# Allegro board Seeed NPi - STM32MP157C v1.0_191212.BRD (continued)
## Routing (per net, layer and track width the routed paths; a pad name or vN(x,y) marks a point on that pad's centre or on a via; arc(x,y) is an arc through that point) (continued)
GND_EARTH: length 211.8
  TOP w0.121: 54.31,12.11 54.9,12.11 55.46,11.55 v1(55.46,10.77)
  TOP w0.375: 1.69,35.81 J2.S1 ; J2.S1 2.95,36.56 ; J2.S1 1.69,37.32 ; 1.94,32.61 J2.S5 0.79,33.76 ; J8.S3 19.86,8.29 ; J8.S3 19.86,4.94 ; J8.S3 21.54,6.61 ; J13.16 39.95,10.17 ; J13.16 38.44,11.67 ; J13.16 38.44,8.67 ; J2.S6 1.94,31.92 ; J2.S6 1.94,29.61 ; J2.S6 0.79,30.76 ; 6.72,4.94 J8.S4 8.4,6.61 ; 21.44,10.17 J13.15 ; J13.15 24.45,10.17 ; J13.15 22.94,8.67 ; 1.69,28.72 J2.S3 1.69,27.21
  TOP w0.381: J1.6 1.67,54.46 ; 1.67,54.46 1.57,54.46 0.54,53.44 ; 1.67,54.46 0.54,55.6 ; 0.92,20.42 0.92,20.92 J4.1 1.15,25.85 1.15,26.24 ; 1.9,39.91 J5.6 1.5,39.91 ; 1.5,50.71 J5.5 1.9,50.71 ; 1.5,50.71 1.49,50.71 0.54,51.66 ; 1.5,50.71 0.54,49.76 ; 55.41,13.81 55.41,13.56 54.31,12.47 J20.3 54.31,12.11 55.41,11.02 ; 55.41,17.62 54.31,18.72 J20.4 54.31,20.49 54.26,20.55 ; 1.7,65.26 0.54,64.11 ; 1.7,65.26 1.54,65.26 0.44,66.36 ; 1.7,65.26 J1.5 ; 1.5,39.91 0.54,40.87 ; 1.5,39.91 1.49,39.91 0.54,38.96 ; 54.9,20.93 54.9,21.1 J18.1 54.9,25.9 54.9,26.26 ; 0.8,78.84 0.84,78.84 J3.1 6.13,84.13 6.13,84.17
  TOP w0.508: J2.S5 v1(1.94,35.02)
  LYR2_GND w0.375: J13.15 24.45,10.17 ; J13.15 21.44,10.17 ; J13.15 22.94,8.67 ; 8.4,6.61 J8.S4 6.72,4.94 ; 1.69,28.72 J2.S3 1.69,27.21 ; J13.16 38.44,11.67 ; J13.16 38.44,8.67 ; J13.16 39.95,10.17 ; J8.S3 19.86,8.29 ; J8.S3 21.54,6.61 ; J8.S3 19.86,4.94 ; J2.S1 1.69,37.32 ; J2.S1 2.95,36.56 ; J2.S1 1.69,35.81
  LYR3 w0.375: 1.69,35.81 J2.S1 ; J2.S1 1.69,37.32 ; J2.S1 2.95,36.56 ; J13.16 38.44,11.67 ; J13.16 38.44,8.67 ; J13.16 39.95,10.17 ; 21.44,10.17 J13.15 ; J13.15 24.45,10.17 ; J13.15 22.94,8.67 ; 1.69,28.72 J2.S3 1.69,27.21 ; 19.86,4.94 J8.S3 ; J8.S3 19.86,8.29 ; J8.S3 21.54,6.61 ; 6.72,4.94 J8.S4 8.4,6.61
  LYR4 w0.375: 22.94,8.67 J13.15 ; J13.15 21.44,10.17 ; J13.15 24.45,10.17 ; 1.69,27.21 J2.S3 1.69,28.72 ; J2.S1 2.95,36.56 ; J2.S1 1.69,35.81 ; J2.S1 1.69,37.32 ; 6.72,4.94 J8.S4 8.4,6.61 ; J13.16 39.95,10.17 ; J13.16 38.44,11.67 ; J13.16 38.44,8.67 ; J8.S3 19.86,8.29 ; J8.S3 19.86,4.94 ; J8.S3 21.54,6.61
  LYR5_PWR w0.375: J2.S1 1.69,37.32 ; J2.S1 1.69,35.81 ; J2.S1 2.95,36.56 ; 1.69,27.21 J2.S3 1.69,28.72 ; J13.15 24.45,10.17 ; J13.15 22.94,8.67 ; J13.15 21.44,10.17 ; 6.72,4.94 J8.S4 8.4,6.61 ; 19.86,4.94 J8.S3 ; J8.S3 19.86,8.29 ; J8.S3 21.54,6.61 ; J13.16 39.95,10.17 ; J13.16 38.44,8.67 ; J13.16 38.44,11.67
  LYR5_PWR w0.508: 6,84.17 6,84 J3.1 0.96,78.97 0.92,78.97 ; 0.92,20.93 0.93,20.93 J4.1 3.5,24.19 1.3,26.39 ; 55.15,26.13 55.13,26.13 J18.1 54.95,21.05 55.15,21.05
  BOTTOM w0.375: 21.44,10.17 J13.15 ; J13.15 24.45,10.17 ; J13.15 22.94,8.67 ; J2.S1 1.69,37.32 ; J2.S1 2.95,36.56 ; J2.S1 1.69,35.81 ; 38.44,8.67 J13.16 ; J13.16 39.95,10.17 ; J13.16 38.44,11.67 ; 6.72,4.94 J8.S4 8.4,6.61 ; 19.86,4.94 J8.S3 ; J8.S3 21.54,6.61 ; J8.S3 19.86,8.29 ; 1.69,27.21 J2.S3 1.69,28.72
  BOTTOM w0.381: 1.05,78.58 1.05,79.05 J3.1 6.04,84.05 6.13,84.05
  vias: v1(0.49,77.36) v1(0.49,72.28) v1(0.49,67.2) v1(0.49,62.12) v1(0.49,57.04) v1(0.49,51.96) v1(0.49,13.23) v1(0.52,46.3) v1(0.52,41.22) v1(0.54,38.6) v1(0.59,35.56) v1(0.54,33.63) v1(0.54,30.76) v1(0.59,20.14) v1(0.57,16.63) v1(0.52,11.63) v1(0.57,9.22) v1(0.54,5.56) v1(0.54,3.27) v1(0.72,26.64) v1(2.01,0.86) v1(3.82,0.68) v1(6.79,4.16) v1(6.97,84.35) v1(8.9,0.68) v1(12.05,84.35) v1(16.26,0.68) v1(17.13,84.35) v1(18.93,4.62) v1(21.09,4.72) v1(21.34,0.68) v1(22.21,84.35) v1(23.3,0.66) v1(27.29,84.35) v1(28.38,0.66) v1(32.37,84.35) v1(33.46,0.66) v1(34.32,84.3) v1(36.25,0.66) v1(39.58,3.73) v1(39.63,7.41) v1(40.8,0.71) v1(45.88,0.71) v1(50.96,0.71) v1(55.46,77.42) v1(55.46,72.34) v1(55.46,67.26) v1(55.46,62.18) v1(55.46,57.1) v1(55.46,52.02) v1(55.46,46.94) v1(55.46,41.86) v1(55.46,36.78) v1(55.46,31.7) v1(55.46,16.74) v1(55.46,5.69)
VBAT: length 41.2
  TOP w0.203: J7.25 44.62,44 v1(44.99,44.37) ; J7.27 v1(44.46,44.4)
  TOP w0.508: v1(44.46,44.4) 44.97,44.4 v1(44.99,44.37)
  LYR3 w0.508: v1(49.31,14.32) 49.3,14.32 v1(48.8,14.32) 48.8,15.59 43.65,20.74 43.65,27.08 v1(48.42,31.85)
  BOTTOM w0.508: v1(44.46,44.4) 44.97,44.4 v1(44.99,44.37) 46.44,44.37 48.81,42 48.81,32.23 v1(48.42,31.85)
26M_XTAL_IN: length 8.4
  TOP w0.254: X1.3 27.45,74.09 C8.1 28.64,74.09 29.04,74.48 29.04,74.49 29.4,74.84 R29.2 29.97,74.84 30.25,75.13 33.59,75.13 33.8,74.91 U3.10
26M_XTAL_OUT: length 4.2
  TOP w0.254: U3.11 29.98,74.06 29.97,74.08 R29.1 R30.1
BOOT0: length 39.1
  TOP w0.121: J10.6 31.45,52 30.89,52.55 24.8,52.55 v1(23.27,51.03) ; R8.2 v1(11.39,67.79)
  LYR3 w0.121: v1(23.27,51.03) 23.91,51.66 23.91,57.5 20.35,61.06 20.35,63.6 20.86,64.11 20.86,66.39 v1(21.24,66.77)
  LYR4 w0.121: v1(11.39,67.79) 11.77,68.17 17.31,68.17 18.7,66.77 v1(21.24,66.77)
BOOT1: length 38.7
  TOP w0.121: v1(23.27,50.39) 25.05,52.17 30.77,52.17 31.34,51.6 J10.8 ; v1(16.54,72.49) 16.19,72.49 16.06,72.36 R12.2
  LYR3 w0.121: v1(23.27,50.39) 24.16,51.28 24.16,57.6 20.58,61.19 20.58,63.34 21.12,63.88 21.12,66.01 21.74,66.64 21.74,67.54 21.37,67.92 v1(21.37,69.06)
  LYR4 w0.121: v1(21.37,69.06) 20.33,69.06 16.9,72.49 v1(16.54,72.49)
BOOT2: length 33.3
  TOP w0.121: v1(24.42,50.77) 25.43,51.79 30.56,51.79 31.15,51.2 J10.10 ; v1(13.24,63.6) 12.48,63.6 11.98,64.1 11.98,64.23 11.45,64.76 R3.2
  LYR3 w0.121: v1(20.99,63.09) 20.99,62.74 20.8,62.55 20.8,61.32 24.42,57.7 v1(24.42,50.77)
  LYR4 w0.121: v1(20.99,63.09) 20.61,62.71 14,62.71 13.49,63.22 13.49,63.35 v1(13.24,63.6)
BOOT_MODE0: length 3.5
  TOP w0.121: R15.1 v1(14.13,71.35)
  BOTTOM w0.121: v1(14.13,71.35) 15.86,71.35 16.32,70.89 Q9.1
BOOT_MODE1: length 7.8
  TOP w0.121: Q2.1 15.24,67.44 ; 15.24,67.44 14.38,66.59 14.38,64.56 14.73,64.21 Q3.1 ; 15.24,67.44 14.73,67.44 14.59,67.57 14.59,69.85 14.64,69.89 R16.2
BT_HOST_WAKE: length 39.2
  TOP w0.121: U3.7 36.5,72.77 37.92,71.36 v1(38.27,71.36) ; v1(41.82,57.76) 41.44,57.38 32.42,57.38 31.28,56.23 28.1,56.23 27.21,55.34 25.05,55.34 24.75,55.64 J14.60
  LYR3 w0.121: v1(41.82,57.76) 41.82,58.11 42.05,58.34 42.05,69.72 40.29,71.47 38.74,71.47 38.62,71.36 v1(38.27,71.36)
BT_RST: length 31.3
  TOP w0.121: J14.56 23.95,55.3 24.42,54.84 27.43,54.84 28.32,55.72 31.66,55.72 32.8,56.87 42.71,56.87 v1(43.09,57.25) ; U3.34 43.09,63.22 v1(42.71,62.84) 43.49,62.05 R47.1
  LYR3 w0.121: v1(42.71,62.84) 43.21,62.33 43.21,57.73 43.09,57.6 v1(43.09,57.25)
BT_UART_CTS: length 2.4
  TOP w0.121: U3.44 42.1,72.87 41.69,72.46 v1(41.69,72.11)
  BOTTOM w0.121: v1(41.69,72.11) 41.44,72.11 41.42,72.09 R76.2
BT_UART_RTS: length 4.5
  TOP w0.121: U3.41 43.14,70.23 43.96,70.23 44.08,70.11 44.08,70.05 v1(44.13,70)
  BOTTOM w0.121: R79.2 43.25,69.12 v1(44.13,70)
BT_UART_RX: length 2.5
  TOP w0.121: U3.43 42.17,71.97 41.69,71.49 v1(41.69,71.13)
  BOTTOM w0.121: R77.2 41.56,71.13 41.56,71.13 v1(41.69,71.13)
BT_UART_TX: length 4.2
  TOP w0.121: U3.42 43.1,71.07 v1(44.05,71.07)
  BOTTOM w0.121: R78.2 43.12,70.14 v1(44.05,71.07)
BT_WAKE: length 40
  TOP w0.121: v1(42.32,57.38) 42.07,57.12 32.55,57.12 31.4,55.98 28.23,55.98 27.34,55.09 24.75,55.09 24.35,55.48 J14.58 ; U3.6 37.4,72.59 37.87,72.11 38.01,72.11 v1(38.26,71.86)
  LYR3 w0.121: v1(38.26,71.86) 38.61,71.86 38.75,71.73 40.48,71.73 42.32,69.88 v1(42.32,57.38)
DSI_CK_N: length 50.8
  TOP w0.095: J10.50 31.51,43.2 31.45,43.14 27.95,43.14 27.22,42.41 27.22,42 v1(26.97,41.75) ; J11.5 22.5,78.9 22.86,78.54 22.86,78.29 v1(22.62,78.04)
  LYR3 w0.102: v1(26.97,41.75) 27.21,41.98 27.21,42.34 27.49,42.62 27.7,42.62 27.97,42.9 27.97,43.79 26.02,45.74 26.02,67.08 22.65,70.45 22.65,71.4 22.55,71.5 22.31,71.5 22.03,71.78 22.03,72.23 22.31,72.51 22.55,72.51 22.65,72.61 22.65,74.49 22.55,74.59 22.03,74.59 21.75,74.87 21.75,75.33 22.03,75.61 22.55,75.61 22.65,75.71 22.65,76.01 22.46,76.2 21.98,76.2 21.65,76.53 21.65,77.11 21.93,77.39 22.72,77.39 22.85,77.52 22.85,77.81 v1(22.62,78.04)
DSI_CK_P: length 50.8
  TOP w0.095: v1(23.38,78.04) 23.14,78.29 23.14,78.55 23.5,78.91 J11.6 ; v1(27.75,41.75) 27.5,42 27.5,42.3 28.06,42.86 31.45,42.86 31.51,42.8 J10.52
  LYR3 w0.102: v1(23.38,78.04) 23.15,77.81 23.15,77.39 22.84,77.09 22.06,77.09 21.95,76.98 21.95,76.65 22.11,76.5 22.59,76.5 22.95,76.14 22.95,75.59 22.67,75.31 22.16,75.31 22.06,75.2 22.06,75 22.16,74.9 22.67,74.9 22.95,74.62 22.95,72.49 22.67,72.21 22.44,72.21 22.33,72.11 22.33,71.9 22.44,71.8 22.67,71.8 22.95,71.52 22.95,70.57 26.32,67.2 26.32,45.87 26.53,45.66 26.81,45.66 26.96,45.52 26.96,45.24 27.1,45.09 27.33,45.09 27.53,44.89 27.53,44.66 27.68,44.51 27.93,44.51 28.11,44.34 28.11,44.09 28.28,43.91 28.28,42.77 27.82,42.31 27.61,42.31 27.51,42.21 27.51,41.98 v1(27.75,41.75)
DSI_D0_N: length 50.9
  TOP w0.095: v1(27.36,39.6) 27.59,39.83 27.59,40.99 28.54,41.94 31.45,41.94 31.51,42 J10.56 ; v1(25.62,78.08) 25.86,78.32 25.86,78.54 25.5,78.9 J11.8
  LYR3 w0.102: v1(27.36,39.6) 27.59,39.83 27.59,40.61 29.24,42.26 29.24,44.5 27.08,46.66 27.08,67.41 23.6,70.89 23.6,75.41 25.78,77.59 25.78,77.91 v1(25.62,78.08)
DSI_D0_P: length 50.8
  TOP w0.095: v1(26.38,78.08) 26.14,78.32 26.14,78.53 26.5,78.89 J11.9 ; J10.58 31.51,41.6 31.45,41.66 28.65,41.66 27.87,40.88 27.87,39.85 v1(28.13,39.6)
  LYR3 w0.102: v1(26.38,78.08) 26.09,77.78 26.09,77.46 23.91,75.28 23.91,71.01 27.39,67.53 27.39,46.78 29.55,44.62 29.55,42.14 29.12,41.7 29.12,41.45 28.96,41.29 28.7,41.29 28.54,41.13 28.54,40.87 28.38,40.71 28.13,40.71 27.9,40.48 27.9,39.83 v1(28.13,39.6)
DSI_D1_N: length 50.8
  TOP w0.095: J11.2 19.5,78.93 19.86,78.57 19.86,78.29 v1(19.62,78.04) ; v1(26.34,43.28) 26.55,43.49 26.55,44.03 26.86,44.34 31.45,44.34 31.51,44.4 J10.44
  LYR3 w0.102: v1(19.62,78.04) 19.85,77.81 19.85,76.8 20.56,76.09 20.56,71.27 25.18,66.65 25.18,66.19 25.08,66.08 24.16,66.08 23.88,65.8 23.88,65.35 24.16,65.07 25.08,65.07 25.18,64.97 25.18,61.02 25.08,60.92 24.62,60.92 24.34,60.64 24.34,60.18 24.62,59.9 25.08,59.9 25.18,59.8 25.18,59.6 25.08,59.5 24.62,59.5 24.34,59.22 24.34,58.76 24.62,58.48 25.08,58.48 25.18,58.38 25.18,45.01 26.58,43.61 26.58,43.51 v1(26.34,43.28)
DSI_D1_P: length 50.8
  TOP w0.095: v1(27.12,43.28) 26.83,43.56 26.83,43.91 26.98,44.06 31.45,44.06 31.51,44 J10.46 ; v1(20.38,78.04) 20.14,78.29 20.14,78.57 20.5,78.93 J11.3
  LYR3 w0.102: v1(27.12,43.28) 26.88,43.51 26.88,43.74 25.48,45.14 25.48,58.5 25.2,58.78 24.75,58.78 24.65,58.89 24.65,59.09 24.75,59.19 25.2,59.19 25.48,59.47 25.48,59.93 25.2,60.21 24.75,60.21 24.65,60.31 24.65,60.51 24.75,60.61 25.2,60.61 25.48,60.89 25.48,65.09 25.2,65.37 24.29,65.37 24.19,65.47 24.19,65.68 24.29,65.78 25.2,65.78 25.48,66.06 25.48,66.77 20.86,71.4 20.86,72.34 21.04,72.52 21.04,72.78 20.86,72.95 20.86,73.16 21.04,73.33 21.04,73.59 20.86,73.77 20.86,73.97 21.04,74.15 21.04,74.4 20.86,74.58 20.86,76.22 20.15,76.93 20.15,77.81 v1(20.38,78.04)
DSI_LCD_BL_CTRL: length 48.7
  TOP w0.121: v1(30.51,39.34) 31.17,40 J10.66 ; v1(36.41,78.3) 36.5,78.4 J11.19
  LYR3 w0.121: v1(36.41,78.3) 35.29,77.19 34.45,77.19 32.29,75.03 32.29,62.83 33.09,62.04 33.09,61.41 34.32,60.17 34.32,58.52 36.48,56.36 36.48,51.58 32.16,47.27 32.16,42.39 30.51,40.74 v1(30.51,39.34)
DSI_LCD_INT: length 49.4
  TOP w0.121: J11.17 34.5,78.33 v1(34.53,78.3) ; J10.62 30.83,40.8 v1(29.37,39.34)
  LYR3 w0.121: v1(29.37,39.34) 29.37,40.36 31.66,42.65 31.66,47.39 35.97,51.71 35.97,55.16 32.64,58.49 32.64,61.85 31.66,62.84 31.66,75.43 v1(34.53,78.3)
DSI_RESET: length 52.4
  TOP w0.121: J10.68 31.5,39.6 v1(30.51,38.61) ; R40.1 38.41,77.39 38.26,77.54 v1(38.26,77.55) 37.5,78.31 J11.20
  LYR3 w0.121: v1(30.51,38.61) 30.89,38.99 30.89,40.74 32.42,42.26 32.42,47.21 36.74,51.52 36.74,56.43 34.57,58.6 34.57,60.31 33.31,61.57 33.31,62.13 32.55,62.89 32.55,74.9 34.45,76.81 37.52,76.81 v1(38.26,77.55)
DSI_TE: length 51.1
  TOP w0.121: v1(35.54,78.25) 35.5,78.3 J11.18 ; J10.64 30.94,40.4 29.88,39.34 29.88,39.09 v1(29.37,38.58)
  LYR3 w0.121: v1(35.54,78.25) 35.01,78.25 32.04,75.28 32.04,62.77 32.86,61.94 32.86,58.58 36.23,55.22 36.23,51.64 31.91,47.33 31.91,42.52 29.88,40.48 29.88,39.09 v1(29.37,38.58)
DVP_D0: length 40.9
  TOP w0.121: J14.45 21.95,60.06 21.32,60.7 21.32,61.54 21.37,61.59 v1(21.37,61.95)
  LYR4 w0.121: v1(4.86,45.06) 2.07,47.85 2.07,58.92 6.36,63.22 12.61,63.22 13.63,62.2 21.12,62.2 v1(21.37,61.95)
  BOTTOM w0.121: v1(4.86,45.06) 4.87,45.06 6.13,45.06
DVP_D1: length 39.6
  TOP w0.121: v1(21.74,61.44) 21.74,60.68 22.35,60.07 J14.47
  LYR4 w0.121: v1(21.74,61.44) 21.35,61.44 20.84,61.95 13.5,61.95 12.48,62.96 6.56,62.96 2.32,58.72 2.32,47.98 4.23,46.06 v1(4.87,46.06)
  BOTTOM w0.121: 6.13,46.06 v1(4.87,46.06)
DVP_D2: length 39.9
  TOP w0.121: v1(22.12,61.93) 22.12,60.68 22.75,60.04 J14.49
  LYR4 w0.121: v1(4.86,47.09) 3.72,47.09 2.57,48.23 2.57,58.52 6.76,62.71 12.42,62.71 13.4,61.72 20.58,61.72 21.24,61.06 21.9,61.06 22.12,61.28 v1(22.12,61.93)
  BOTTOM w0.121: 6.13,47.06 4.88,47.06 v1(4.86,47.09)
DVP_D3: length 37.9
  TOP w0.121: v1(22.52,61.43) 22.52,60.8 23.15,60.17 J14.51
  LYR4 w0.121: v1(4.9,48.06) 4.01,48.06 2.83,49.25 2.83,58.39 6.89,62.46 12.36,62.46 13.31,61.5 20.42,61.5 21.12,60.8 22.24,60.8 22.52,61.08 v1(22.52,61.43)
  BOTTOM w0.121: 6.13,48.06 v1(4.9,48.06)
DVP_D4: length 38
  TOP w0.121: v1(22.92,61.92) 22.92,60.78 23.55,60.15 J14.53
  LYR4 w0.121: v1(4.86,48.99) 3.84,48.99 3.05,49.79 3.05,58.23 7.02,62.2 12.3,62.2 13.22,61.28 20.32,61.28 21.06,60.55 22.3,60.55 22.92,61.17 v1(22.92,61.92)
  BOTTOM w0.121: v1(4.86,48.99) 4.93,49.06 6.13,49.06
DVP_D5: length 35.6
  TOP w0.121: J14.55 23.95,60.17 23.32,60.8 v1(23.32,61.4)
  LYR4 w0.121: v1(23.32,61.4) 23.32,60.85 22.77,60.3 20.86,60.3 20.1,61.06 9.56,61.06 9.05,61.57 6.76,61.57 3.27,58.07 3.27,50.83 3.97,50.14 v1(4.86,50.14)
  BOTTOM w0.121: J22.7 4.93,50.06 v1(4.86,50.14)
DVP_D6: length 35.9
  TOP w0.121: J14.57 24.35,60.3 23.72,60.93 23.72,61.53 23.69,61.56 v1(23.69,61.91)
  LYR4 w0.121: v1(4.9,51.06) 4.18,51.06 3.49,51.76 3.49,57.86 6.3,60.67 12.03,60.67 12.84,59.86 14.97,59.86 15.88,60.78 20.06,60.78 20.8,60.04 23.2,60.04 23.69,60.54 v1(23.69,61.91)
  BOTTOM w0.121: J22.8 v1(4.9,51.06)
DVP_D7: length 38.3
  TOP w0.121: v1(24.09,61.43) 24.09,61.38 24.12,61.36 24.12,60.93 24.75,60.3 J14.59
  LYR4 w0.121: v1(4.88,52.06) 4.2,52.06 3.72,52.55 3.72,57.63 5.93,59.84 7.68,59.84 8.14,60.3 11.97,60.3 12.73,59.53 15.76,59.53 15.88,59.65 15.88,60.12 16,60.25 16.24,60.25 16.36,60.12 16.36,59.56 16.48,59.44 16.72,59.44 16.84,59.56 16.84,60.12 16.97,60.25 17.21,60.25 17.33,60.12 17.33,59.56 17.45,59.44 17.69,59.44 17.81,59.56 17.81,60.12 17.93,60.25 18.17,60.25 18.29,60.12 18.29,59.56 18.41,59.44 18.65,59.44 18.78,59.56 18.78,60.12 18.9,60.25 19.14,60.25 19.26,60.12 19.26,59.83 19.38,59.71 23.6,59.71 24.09,60.2 v1(24.09,61.43)
  BOTTOM w0.121: J22.9 v1(4.88,52.06)
DVP_HSYNC: length 35
  TOP w0.121: J14.61 25.15,60.55 24.52,61.19 v1(24.52,61.92)
  LYR4 w0.121: v1(24.52,61.92) 24.52,59.99 23.75,59.22 12.63,59.22 11.86,59.99 11.53,59.99 11.41,59.87 11.41,59.65 11.29,59.53 11.05,59.53 10.93,59.65 10.93,59.87 10.81,59.99 10.57,59.99 10.45,59.87 10.45,59.65 10.33,59.53 10.09,59.53 9.97,59.65 9.97,59.87 9.84,59.99 9.6,59.99 9.48,59.87 9.48,59.65 9.36,59.53 9.12,59.53 9,59.65 9,59.87 8.88,59.99 8.31,59.99 7.88,59.56 6.03,59.56 3.97,57.5 3.97,53.95 v1(4.86,53.06)
  BOTTOM w0.121: J22.10 6.12,53.06 v1(4.86,53.06)
DVP_PCLK: length 33.6
  TOP w0.121: J14.65 25.95,58.39 25.44,57.88 v1(24.76,57.88)
  LYR4 w0.121: v1(24.76,57.88) 24.34,57.88 24.22,58 24.22,58.75 24.09,58.87 23.85,58.87 23.73,58.75 23.73,58 23.61,57.88 23.37,57.88 23.25,58 23.25,58.75 23.13,58.87 22.89,58.87 22.77,58.75 22.77,58 22.65,57.88 20.94,57.88 20.14,58.68 14.06,58.68 13.94,58.56 13.94,58.21 13.82,58.09 13.58,58.09 13.46,58.21 13.46,58.56 13.34,58.68 13.09,58.68 12.97,58.56 12.97,58.21 12.85,58.09 12.61,58.09 12.49,58.21 12.49,58.56 12.37,58.68 12.13,58.68 12.01,58.56 12.01,58.21 11.89,58.09 11.65,58.09 11.53,58.21 11.53,58.56 11.4,58.68 11.16,58.68 11.04,58.56 11.04,58.21 10.92,58.09 10.68,58.09 10.56,58.21 10.56,58.55 10.44,58.67 7.3,58.67 5.27,56.64 4.71,56.64 4.48,56.41 4.48,55.47 v1(4.88,55.07)
  BOTTOM w0.121: J22.12 v1(4.88,55.07)
DVP_PWDN: length 27.7
  TOP w0.121: v1(24.42,62.58) 24.77,62.58 26.75,60.6 J14.69
  LYR4 w0.121: v1(5.62,63.88) 6.31,63.88 6.71,63.47 12.73,63.47 13.72,62.49 20.7,62.49 20.79,62.58 v1(24.42,62.58)
  BOTTOM w0.121: v1(5.62,63.88) 5.14,63.88 4.73,63.47 4.73,62.18 4.85,62.07 J22.19
DVP_RST: length 73
  TOP w0.121: v1(47.28,42.64) 47.58,42.95 47.68,42.95 48.67,43.94 48.67,47.6 48.42,47.85 47.95,47.85 47.8,48 J7.46
  LYR3 w0.121: v1(7.4,53.57) 6.64,54.33 6.64,62.33 v1(8.29,63.98)
  LYR4 w0.121: v1(47.28,42.64) 46.92,42.64 46.87,42.7 39.08,42.7 38.01,41.63 35.47,41.63 34.2,42.9 28.86,42.9 27.97,43.79 20.48,43.79 17.59,46.68 13.46,46.68 12.61,45.82 7.49,45.82 6.89,46.42 6.89,53.06 v1(7.4,53.57)
  BOTTOM w0.121: v1(8.29,63.98) 7.37,63.07 J22.20
DVP_VSYNC: length 34.1
  TOP w0.121: v1(22.13,58.26) 25.42,58.26 25.55,58.39 J14.63
  LYR4 w0.121: v1(4.86,54.07) 4.22,54.71 4.22,57.38 4.67,57.82 4.84,57.82 5.29,57.37 5.46,57.37 5.63,57.54 5.63,57.71 5.19,58.15 5.19,58.34 5.36,58.51 5.56,58.51 6,58.07 6.17,58.07 6.34,58.25 6.34,58.42 5.89,58.87 5.89,59.04 6.08,59.23 7.3,59.23 7.42,59.11 7.42,59.05 7.54,58.92 7.79,58.92 7.91,59.05 7.91,59.11 8.03,59.23 8.27,59.23 8.39,59.11 8.39,59.05 8.51,58.92 8.75,58.92 8.87,59.05 8.87,59.11 8.99,59.23 9.23,59.23 9.35,59.11 9.35,59.05 9.48,58.92 9.72,58.92 9.84,59.05 9.84,59.11 9.96,59.23 10.2,59.23 10.32,59.11 10.32,59.05 10.44,58.92 10.68,58.92 10.8,59.05 10.8,59.11 10.92,59.23 11.16,59.23 11.28,59.11 11.28,59.05 11.41,58.92 11.65,58.92 11.77,59.05 11.77,59.11 11.89,59.23 12.2,59.23 12.48,58.95 20.88,58.95 21.05,58.78 21.05,58.38 21.17,58.26 21.41,58.26 21.53,58.38 21.53,58.78 21.65,58.9 22.01,58.9 22.13,58.78 v1(22.13,58.26)
  BOTTOM w0.121: v1(4.86,54.07) 4.87,54.07 J22.11
ETH1_LDO_O: length 21.3
  TOP w0.121: v1(32.52,36.77) 22.54,36.77 v1(21.37,37.94)
  LYR3 w0.121: v1(21.37,37.94) 20.99,38.33 v1(20.99,44.29)
  BOTTOM w0.121: U5.43 20.69,43.99 v1(20.99,44.29) ; Q6.1 v1(32.52,36.77)
ETH1_RESETN: length 14.2
  LYR3 w0.121: v1(20.32,44.49) 19.97,44.15 19.97,38.45 v1(20.48,37.94)
  BOTTOM w0.121: v1(20.48,37.94) R108.2 20.48,36.67 D10.1 19.59,34.9 19.64,34.85 C65.1 20.21,33.54 20.29,33.62 21.01,33.62 21.2,33.82 U8.4 ; U5.42 v1(20.32,44.49)
ETH_CLK125: length 22.8
  TOP w0.121: J14.11 15.15,58.13 15.66,57.62 15.66,57.6 15.88,57.38 21.02,57.38 21.14,57.5 v1(21.5,57.5)
  LYR3 w0.121: v1(23.91,46.33) 23.66,46.58 23.66,48.13 22.13,49.65 22.13,50.52 22.77,51.15 22.77,56.23 v1(21.5,57.5)
  BOTTOM w0.121: v1(23.91,46.33) 24.54,45.7 24.54,45.43 ; 24.54,45.43 24.16,45.43 24.13,45.4 23.69,45.4 23.6,45.49 R95.1 ; 24.54,45.43 C73.1
ETH_GTX_CLK: length 4
  TOP w0.121: R48.1 13.86,61.54 14.36,61.04 14.9,61.04 15.38,60.56 16.04,60.56 16.35,60.24 J14.17
ETH_MDC: length 17.1
  TOP w0.121: J14.31 19.15,58.48 19.09,58.42 19.09,58.24 19.08,58.24 v1(19.08,57.88)
  LYR3 w0.121: v1(19.08,57.88) 19.08,58.91 19.2,59.03 20.86,59.03 21.12,58.77 21.12,57.38 21.12,57.37 21.12,57.35 22.51,55.96 22.51,51.35 21.86,50.69 21.86,49.39 v1(22.77,48.49)
  BOTTOM w0.121: R73.1 22.72,48.43 v1(22.77,48.49) 22.82,48.43 R74.2
ETH_MDINT: length 16.1
  TOP w0.121: v1(20.35,57.88) 20.75,58.28 J14.39
  LYR3 w0.121: v1(20.35,57.88) 20.35,57.38 22.04,55.69 22.04,51.56 21.37,50.9 21.37,47.32 21.49,47.21 v1(21.49,46.86)
  BOTTOM w0.121: U5.38 20.65,46.49 21.01,46.86 v1(21.49,46.86) 21.5,46.85 21.5,46.83 21.55,46.79 R89.2
ETH_MDIO: length 16.2
  TOP w0.121: v1(19.46,58.26) 19.46,58.39 19.55,58.48 J14.33
  LYR3 w0.121: v1(19.46,58.26) 19.46,58.62 19.62,58.77 20.48,58.77 20.73,58.52 20.73,57.38 22.26,55.85 22.26,51.41 21.64,50.78 21.64,48.6 v1(22.77,47.47)
  BOTTOM w0.121: R84.1 22.72,47.42 v1(22.77,47.47) 22.82,47.42 R85.2
ETH_NRST: length 32.6
  TOP w0.121: J14.37 20.35,58.39 20.23,58.27 20.1,58.27 20.09,58.26 20.07,58.26 19.85,58.04 19.85,58.02 19.85,58.01 v1(19.85,57.88)
  LYR3 w0.121: v1(19.85,57.88) 19.85,57.53 21.72,55.66 21.72,51.63 21.12,51.03 21.12,47.02 21.11,47.01 21.11,46.7 23.53,44.29 v1(23.53,30.18)
  BOTTOM w0.121: v1(23.53,30.18) 23.18,29.84 R129.1
ETH_RX_CLK: length 13.2
  TOP w0.121: J14.13 15.55,58.24 v1(16.04,57.76)
  LYR3 w0.121: v1(19.85,52.8) 19.06,52.8 18.7,53.16 18.7,53.67 18.58,53.79 18.29,53.79 18.17,53.67 18.17,53.47 18.08,53.39 17.72,53.39 17.64,53.47 17.64,53.92 17.48,54.07 15.71,54.07 15.25,54.53 15.25,55.29 16.04,56.08 v1(16.04,57.76)
  BOTTOM w0.121: v1(19.85,52.8) 19.9,52.75 C28.1 R61.1
ETH_RX_DV: length 11
  TOP w0.121: v1(14.77,60.3) 14.75,60.28 J14.9
  LYR3 w0.121: v1(14.77,60.3) 15.17,60.3 15.6,59.86 15.6,56.11 14.89,55.39 14.89,54.35 15.68,53.57 v1(17.18,53.57)
  BOTTOM w0.121: R53.1 v1(17.18,53.57)
ETH_RXD0: length 13.4
  TOP w0.121: v1(13.11,60.3) 13.15,60.26 J14.1
  LYR3 w0.121: v1(16.8,52.8) 16.16,52.17 13.88,52.17 12.86,53.18 12.86,60.04 v1(13.11,60.3)
  BOTTOM w0.121: R59.1 16.85,52.75 v1(16.8,52.8)
ETH_RXD1: length 13.2
  TOP w0.121: J14.3 13.55,60.27 13.5,60.32 v1(13.5,60.68)
  LYR3 w0.121: v1(13.5,60.68) 13.5,59.94 13.17,59.61 13.17,59.33 13.29,59.21 13.48,59.21 13.6,59.08 13.6,58.84 13.48,58.72 13.29,58.72 13.17,58.6 13.17,53.36 14.11,52.42 15.4,52.42 v1(15.78,52.8)
  BOTTOM w0.121: v1(15.78,52.8) 15.83,52.75 R58.1
ETH_RXD2: length 13.4
  TOP w0.121: v1(13.98,60.3) 13.95,60.27 J14.5
  LYR3 w0.121: v1(13.98,60.3) 13.98,59.95 13.9,59.87 13.9,58.42 13.78,58.3 13.59,58.3 13.47,58.18 13.47,57.94 13.59,57.82 13.78,57.82 13.9,57.7 13.9,57.46 13.78,57.34 13.59,57.34 13.47,57.22 13.47,56.98 13.59,56.86 13.78,56.86 13.9,56.74 13.9,56.51 13.78,56.39 13.59,56.39 13.47,56.27 13.47,56.03 13.59,55.91 13.78,55.91 13.9,55.79 13.9,55.52 13.5,55.11 13.5,54.4 13.65,54.25 14.54,54.25 14.69,54.1 14.69,53.74 14.56,53.62 14.03,53.62 13.91,53.5 13.91,53.02 14.13,52.8 v1(14.77,52.8)
  BOTTOM w0.121: R57.1 14.82,52.75 v1(14.77,52.8)
ETH_RXD3: length 13.1
  TOP w0.121: J14.7 14.35,60.28 14.38,60.31 v1(14.38,60.66)
  LYR3 w0.121: v1(14.38,60.66) 14.38,59.57 14.51,59.45 14.87,59.45 14.99,59.33 14.99,59.09 14.87,58.97 14.51,58.97 14.38,58.84 14.38,58.62 14.51,58.5 14.9,58.5 15.02,58.38 15.02,58.14 14.9,58.02 14.51,58.02 14.38,57.9 14.38,56.94 14.51,56.82 14.92,56.82 15.04,56.7 15.04,56.46 14.92,56.34 14.4,56.34 14.26,56.19 14.26,55.45 13.87,55.06 v1(13.87,54.71)
  BOTTOM w0.121: R56.1 13.8,52.75 13.75,52.8 13.75,53.85 13.87,53.97 v1(13.87,54.71)
ETH_TX_EN: length 2.3
  TOP w0.121: J14.27 18.35,61.01 18.5,61.16 R41.1
ETH_TXD0: length 3.6
  TOP w0.121: R46.1 14.75,61.54 15.49,60.8 16.29,60.8 16.75,60.34 J14.19
ETH_TXD1: length 3.1
  TOP w0.121: J14.21 17.15,60.32 16.42,61.06 16.12,61.06 15.64,61.54 R45.1
ETH_TXD2: length 2.7
  TOP w0.121: R44.1 16.53,61.54 17.55,60.52 J14.23
ETH_TXD3: length 2.5
  TOP w0.121: R43.1 17.54,61.54 17.95,61.13 J14.25
EXT_12V: length 22.8
  LYR4 w0.305: v1(46.64,15.08) 46.64,17.75 41.99,22.4 v1(41.99,35.45)
  BOTTOM w0.305: R158.1 v1(41.99,35.45)
GATE: length 10.2
  BOTTOM w0.121: R159.1 40.55,35.05 40.56,35.04 D16.2 ; R159.1 40.61,35.43 40.85,35.67 40.99,35.67 41.24,35.92 41.24,35.98 41.48,36.22 R158.2 ; R159.1 38.19,35.43 37.93,35.69 37.23,35.69 ; Q7.1 37.23,35.69 ; 37.23,35.69 38.01,36.46 38.01,38.07 37.23,38.84 Q8.1
GBE1_LED_ACT: length 57.3
  LYR3 w0.305: v1(11.46,43.66) 9.91,42.11 9.91,37.14 13.98,33.08 13.98,29.84 16.24,27.58 16.24,23.39 21.47,18.16 21.47,15.36 27.59,9.24 v1(27.59,4.42)
  BOTTOM w0.305: U5.17 11.63,43.49 v1(11.46,43.66) 11.44,43.68 R106.1 ; v1(27.59,4.42) 32.59,4.42 J13.13
GBE1_LED_LINK: length 50.8
  LYR3 w0.305: J13.12 28.1,3.72 28.1,9.5 21.88,15.72 21.88,18.51 16.65,23.75 16.65,27.75 14.38,30.01 14.38,33.25 10.32,37.31 10.32,41.37 v1(11.46,42.52)
  BOTTOM w0.305: U5.15 11.61,42.49 11.59,42.52 v1(11.46,42.52) 11.21,42.52 10.93,42.8 R107.1
GBE1_TRN0: length 34
  LYR3 w0.102: J13.2 26.03,13.69 26.03,14.64 26.5,15.11 26.5,18.56 18.63,26.44 18.63,33.83 16.79,35.67 16.25,35.67 v1(16.01,35.9)
  BOTTOM w0.095: v1(16.01,35.9) 16.26,35.66 16.54,35.66 16.8,35.66 18.07,36.93 18.07,40.19 17.96,40.3 U5.3
GBE1_TRN1: length 33.8
  LYR3 w0.102: v1(16.29,38.44) 16.52,38.21 16.79,38.21 17.31,37.7 17.31,36.67 19.72,34.26 19.72,27.02 29.17,17.57 29.17,15.34 28.79,14.96 J13.4
  BOTTOM w0.095: v1(16.29,38.44) 16.53,38.2 16.63,38.2 16.72,38.29 16.72,39.16 16.57,39.31 16.57,40.19 16.46,40.3 U5.6
GBE1_TRN2: length 39.6
  LYR3 w0.102: v1(15.33,39.15) 15.56,39.38 15.56,39.65 15.84,39.93 17.02,39.93 18.25,38.71 18.25,37.13 20.61,34.77 20.61,28.04 23.91,24.74 26.7,24.74 34.26,17.18 34.26,15.07 33.61,14.42 33.61,13.73 J13.8
  BOTTOM w0.095: U5.8 15.46,40.3 15.57,40.19 15.57,39.39 v1(15.33,39.15)
GBE1_TRN3: length 44.1
  LYR3 w0.102: v1(13.83,39.72) 14.06,39.95 14.06,40.54 14.38,40.87 18.07,40.87 19.13,39.8 19.13,37.64 21.62,35.15 21.62,28.67 24.42,25.88 28.1,25.88 37.24,16.74 37.24,15.41 36.41,14.58 J13.10
  BOTTOM w0.095: U5.11 13.96,40.3 14.07,40.19 14.07,39.97 v1(13.83,39.72)
GBE1_TRP0: length 34.1
  LYR3 w0.102: v1(16.01,35.14) 16.24,35.37 16.66,35.37 18.32,33.7 18.32,26.31 26.2,18.44 26.2,15.24 25.97,15.01 25.2,15.01 24.98,15.23 J13.1
  BOTTOM w0.095: U5.2 18.46,40.3 18.35,40.19 18.35,36.82 16.91,35.38 16.66,35.38 16.26,35.38 v1(16.01,35.14)
GBE1_TRP1: length 33.9
  LYR3 w0.102: v1(16.29,37.68) 16.52,37.91 16.66,37.91 17,37.57 17,36.55 19.41,34.13 19.41,26.9 28.86,17.45 28.86,15.47 28.53,15.13 27.69,15.13 27.52,15.31 J13.3
  BOTTOM w0.095: U5.5 16.96,40.3 16.85,40.19 16.85,39.43 17,39.28 17,38.18 16.74,37.92 16.53,37.92 v1(16.29,37.68)
GBE1_TRP2: length 39.5
  LYR3 w0.102: v1(16.1,39.15) 15.87,39.38 15.87,39.52 15.97,39.62 16.9,39.62 17.14,39.38 17.14,39.12 17.3,38.96 17.56,38.96 17.94,38.58 17.94,37 20.3,34.64 20.3,27.91 23.78,24.43 26.58,24.43 33.96,17.05 33.96,15.2 33.36,14.6 32.8,14.6 32.6,14.8 J13.7
  BOTTOM w0.095: v1(16.1,39.15) 15.85,39.39 15.85,40.19 15.96,40.3 U5.7
GBE1_TRP3: length 44
  LYR3 w0.102: v1(14.6,39.72) 14.37,39.95 14.37,40.41 14.51,40.56 17.94,40.56 18.83,39.67 18.83,37.51 21.32,35.02 21.32,28.55 24.29,25.57 27.97,25.57 36.94,16.61 36.94,15.54 36.08,14.68 35.39,14.68 35.14,14.93 J13.9
  BOTTOM w0.095: v1(14.6,39.72) 14.35,39.97 14.35,40.19 14.46,40.3 U5.10
GPIO_PD10: length 24.8
  TOP w0.121: J14.24 17.55,55.6 17.43,55.49 17.43,55.09 v1(17.18,54.84) ; v1(9.67,49.36) 9.28,49.76 7.81,49.76 6.89,48.84 6.89,42.9 7.48,42.31 J5.1
  LYR4 w0.121: v1(9.67,49.36) 10.19,49.88 10.19,51.35 13.16,54.31 16.65,54.31 v1(17.18,54.84)
  BOTTOM w0.121: D2.1 9.67,49.51 v1(9.67,49.36)
GPIO_PE6: length 41
  TOP w0.121: C94.1 17.21,75.32 17.22,75.33 R164.2 17.66,75.82 v1(17.43,76.04) ; SW3.2 13.38,81.6 13.39,81.6 13.39,79.85 13.38,79.85 SW3.4 v1(13.38,77.96) ; v1(21.34,53.32) 21.34,53.67 21.55,53.88 J14.44
  LYR3 w0.121: v1(21.34,53.32) 21.34,53.67 21.5,53.82 21.5,55.22 19.21,57.5 18.83,57.5 18.58,57.76 18.58,59.66 19.81,60.9 19.81,63.98 20.35,64.52 v1(20.35,69.95)
  LYR4 w0.121: v1(20.35,69.95) 16.92,73.38 16.92,75.54 v1(17.43,76.04) 16.8,76.68 15.53,76.68 14.24,77.96 v1(13.38,77.96)
GPIO_PF3: length 9.9
  TOP w0.121: J7.54 v1(48.83,49.6)
  LYR4 w0.121: J19.26 52.56,47.39 52.56,48.83 51.63,49.76 49.34,49.76 49.19,49.6 v1(48.83,49.6)
GPIO_PH15: length 65.2
  TOP w0.121: J14.38 20.35,55.33 20.35,55.33 v1(20.35,54.96)
  LYR3 w0.121: v1(10.96,39.98) 10.96,37.12 14.7,33.38 14.7,30.2 17.05,27.84 17.05,23.85 21.88,19.02 v1(23.02,19.02)
  LYR4 w0.121: v1(20.35,54.96) 18.82,56.49 8.09,56.49 6,54.4 6,44.93 v1(10.96,39.98)
  BOTTOM w0.121: R13.1 25.92,21.92 v1(23.02,19.02)
GPIO_PI0: length 36.8
  TOP w0.121: J14.36 19.95,54.6 20.86,53.69 v1(20.86,52.93) ; v1(26.09,22.93) 26.09,25.6 23.91,27.78 23.91,28.93 23.79,29.05 v1(23.78,29.05)
  LYR3 w0.121: v1(20.86,52.93) 20.61,52.68 20.61,46.83 23.15,44.29 23.15,29.69 v1(23.78,29.05)
  BOTTOM w0.121: R14.1 v1(26.09,22.93)
GPIO_PI1: length 38.6
  TOP w0.121: v1(23.27,28.67) 23.65,28.3 23.65,27.69 25.43,25.91 25.43,21.94 v1(26.07,21.31) ; v1(20.35,53.31) 20.35,53.69 19.55,54.49 J14.34
  LYR3 w0.121: v1(23.27,28.67) 22.92,29.03 22.92,29.4 22.93,29.4 22.93,44.14 20.35,46.71 v1(20.35,53.31)
  BOTTOM w0.121: R134.1 26.3,20.99 26.07,21.22 v1(26.07,21.31)
GPIO_PI4: length 23
  TOP w0.121: v1(17.04,55.37) 17.04,55.37 17.15,55.48 J14.22 ; v1(9.05,49.37) 7.78,49.37 7.15,48.74 7.15,44.68 7.51,44.31 J5.2
  LYR4 w0.121: v1(17.04,55.37) 17.18,55.37 17.55,54.99 17.55,54.68 16.95,54.07 13.37,54.07 10.57,51.28 10.57,49.63 9.93,48.98 9.44,48.98 v1(9.05,49.37)
  BOTTOM w0.121: D3.1 9.05,49.88 v1(9.05,49.37)
HOST_USB1_DM: length 9.4
  TOP w0.114: U1.6 14.99,16.56 15.25,16.3 15.25,16.07 14.36,15.19 14.36,14.77 v1(14.11,14.53) 14.36,14.28 14.36,14.06 13.22,12.91 13.22,12.42 12.74,11.94 J8.A2
  BOTTOM w0.114: v1(14.11,14.53) 14.38,14.8 14.38,15.47 14.21,15.64 L4.2 14.12,16.03 R72.2
HOST_USB1_DP: length 9.3
  TOP w0.114: U1.1 15.68,16.56 15.53,16.41 15.53,15.96 14.64,15.07 14.64,14.77 v1(14.88,14.53) 14.64,14.28 14.64,13.94 13.5,12.8 13.5,12.32 13.87,11.94 J8.A3
  BOTTOM w0.114: v1(14.88,14.53) 14.66,14.75 14.66,15.36 15.06,15.76 L4.3 15.13,16.01 R80.2
HOST_USB1_VBUS: length 1.4
  TOP w0.381: C2.1 v1(10.24,22.48)
  vias: v1(9.81,22.45)
HOST_USB2_DM: length 17.9
  TOP w0.114: U7.6 19.4,16.55 19.59,16.35 19.59,15.98 19.48,15.87 19.4,15.87 19.29,15.75 19.29,15.53 19.4,15.41 19.48,15.41 19.59,15.3 19.59,14.96 19.04,14.4 18.47,14.4 v1(18.19,14.68) 17.95,14.44 16.78,14.44 15.4,13.07 15.4,11.39 15.08,11.07 13.75,11.07 13.19,10.51 13.19,10.05 12.46,9.32 J8.B2
  BOTTOM w0.114: v1(18.19,14.68) 17.95,14.44 17.95,14.31 17.83,14.2 17.18,14.2 16.98,14.4 16.98,14.67 17.2,14.9 17.2,15.13 16.98,15.36 16.98,15.69 L5.1 17.24,15.96 R86.1
HOST_USB2_DP: length 17.9
  TOP w0.114: J8.B3 13.74,9.32 13.47,9.6 13.47,10.4 13.87,10.79 15.2,10.79 15.68,11.27 15.68,12.95 16.18,13.45 16.34,13.45 16.35,13.45 16.51,13.45 16.67,13.61 16.67,13.77 16.67,13.77 16.67,13.94 16.89,14.16 17.95,14.16 v1(18.19,13.92) 18.4,14.12 19.15,14.12 19.87,14.84 19.87,16.28 20.14,16.55 U7.1
  BOTTOM w0.114: v1(18.19,13.92) 17.03,13.92 16.67,14.27 16.67,15.46 16.37,15.76 L5.4 16.28,16.03 R87.1
HOST_USB2_VBUS:
  vias: v1(12.99,21.31) v1(12.99,20.8)
HP_L: length 39.9
  LYR4 w0.305: v1(8.54,64.74) 9.94,64.74 10.47,64.22 10.53,64.22 10.53,64.21 21.4,64.21 21.71,63.9 v1(22.16,63.9)
  BOTTOM w0.254: R176.1 3.82,72.84 3.4,72.43 CON1.5
  BOTTOM w0.305: v1(22.16,63.9) 25.03,66.77 27.47,66.77 27.99,67.3 29.4,67.3 FB1.2 ; CON1.5 6.2,69.95 6.21,69.95 6.76,69.95 7.27,69.44 7.27,65.57 8.1,64.74 v1(8.54,64.74) 9.18,64.74 9.62,64.29 U14.6
HP_R: length 32.5
  LYR4 w0.305: v1(22.77,63.85) 22.77,64.3 22.45,64.61 10.7,64.61 9.94,65.38 8.8,65.38 v1(8.54,65.63)
  BOTTOM w0.305: FB2.2 27.82,66.04 27.59,66.27 25.18,66.27 v1(22.77,63.85) ; U14.1 9.62,66.08 9.18,65.63 v1(8.54,65.63) 8.16,65.63 7.91,65.88 7.91,69.31 8.64,70.05 CON1.3
I2C1_SCL: length 83.6
  TOP w0.121: R18.2 21.75,75.54 22.64,76.43 v1(26.07,76.43) 27.07,77.42 27.07,77.81 27.48,78.23 28.28,78.23 28.5,78.45 J11.11 ; J7.31 v1(45.23,45.2)
  LYR3 w0.121: v1(50.2,45.06) 52.36,45.06 J19.28 ; v1(45.23,45.2) 44.98,45.45 44.98,53.45 44.1,54.33 41.67,54.33 41.31,54.69 41.31,56.8 40.67,57.44 40.67,64.61 40.93,64.87 40.93,65.76 v1(40.55,66.14) ; v1(33.82,72.87) 35.21,71.47 35.21,68.11 34.7,67.6 34.7,66.9 v1(34.96,66.65)
  LYR4 w0.121: v1(26.07,76.43) 28.74,73.76 32.93,73.76 v1(33.82,72.87) ; v1(34.96,66.65) 40.04,66.65 v1(40.55,66.14) ; v1(50.2,45.06) 49.85,45.06 49.71,45.2 v1(45.23,45.2)
  BOTTOM w0.121: U11.17 33.71,56.97 32.8,57.88 32.8,59.15 30.64,61.31 30.64,63.09 31.4,63.85 32.8,63.85 33.31,64.36 33.31,65.76 34.19,66.64 34.32,66.64 34.32,66.65 v1(34.96,66.65)
I2C1_SDA: length 79.9
  TOP w0.121: J11.12 29.5,78.48 29,77.98 27.59,77.98 27.31,77.71 27.31,77.29 26.45,76.42 26.45,76.14 26.22,75.92 v1(25.69,75.92) 25.43,76.17 23.15,76.17 22.64,75.66 R21.2 ; J7.33 44.29,45.6 v1(44.38,45.69)
  LYR3 w0.121: v1(40.54,65.5) 40.54,65.15 40.42,65.03 40.42,57.38 41.05,56.74 41.05,54.58 41.56,54.07 43.98,54.07 44.72,53.32 44.72,48.78 44.74,48.77 44.74,46.04 v1(44.38,45.69) ; v1(33.05,72.87) 34.96,70.96 34.96,68.17 34.45,67.66 v1(34.45,66.27)
  LYR4 w0.121: v1(33.05,72.87) 32.42,73.5 28.68,73.5 26.26,75.92 v1(25.69,75.92) ; J19.27 51.24,44.65 50.2,45.69 v1(44.38,45.69) ; v1(34.45,66.27) 39.78,66.27 v1(40.54,65.5)
  BOTTOM w0.121: U11.18 33.59,57.48 33.18,57.88 33.18,59.28 31.02,61.44 31.02,62.96 31.53,63.47 32.8,63.47 33.56,64.23 33.56,65.5 34.07,66.02 34.2,66.02 v1(34.45,66.27)
I2C2_SCL: length 46.6
  TOP w0.121: v1(36.86,46.58) 36.52,46.58 36.3,46.8 J10.31
  LYR3 w0.121: v1(7.53,60.3) 7.15,59.92 7.15,54.84 8.03,53.95 8.03,52.3 v1(8.42,51.91)
  LYR4 w0.121: v1(8.42,51.91) 8.42,50.77 8.67,50.52 8.67,49.23 9.16,48.74 11.72,48.74 12.26,49.28 13.46,49.28 14.65,48.09 18.12,48.09 18.13,48.1 24.04,48.1 24.54,47.6 28.74,47.6 29.5,46.83 31.66,46.83 32.16,47.34 35.59,47.34 36.36,46.58 v1(36.86,46.58)
  BOTTOM w0.121: J22.17 7.41,60.07 7.53,60.19 v1(7.53,60.3) 8.24,60.3 8.39,60.14 R172.2
I2C2_SDA: length 48.9
  TOP w0.121: J10.33 36.35,46.4 36.67,46.08 37.12,46.08 v1(37.37,46.33)
  LYR3 w0.121: v1(7.78,51.91) 7.78,53.89 6.89,54.77 6.89,60.56 v1(7.39,61.07)
  LYR4 w0.121: v1(37.37,46.33) 37.12,46.08 36.35,46.08 35.31,47.12 32.26,47.12 31.75,46.61 29.34,46.61 28.61,47.34 24.45,47.34 23.91,47.88 18.23,47.88 18.21,47.87 14.5,47.87 13.3,49.06 12.42,49.06 11.84,48.49 9.1,48.49 8.42,49.17 8.42,50.26 8.41,50.27 8.41,50.29 8.03,50.67 8.03,51.66 v1(7.78,51.91)
  BOTTOM w0.121: R173.2 7.78,61.1 7.74,61.07 v1(7.39,61.07) J22.18
I2C4_SCL: length 64.3
  TOP w0.121: J1.1 9.23,56.17 9.05,55.99 9.05,54.86 9.23,54.68 v1(9.23,54.33) ; J14.18 16.35,55.48 16.29,55.42 v1(16.29,54.96)
  LYR3 w0.121: v1(18.83,67.28) 19.46,66.65 19.46,64.87 19.08,64.49 19.08,61.31 17.56,59.79 17.56,56.61 16.29,55.34 v1(16.29,54.96)
  LYR4 w0.121: v1(16.29,54.96) 15.65,55.6 14.13,55.6 12.86,54.33 v1(9.23,54.33) ; J19.5 49.54,71.57 v1(48.55,70.58) 48.14,70.58 47.96,70.41 45.7,70.41 42.45,67.15 19.31,67.15 19.18,67.28 v1(18.83,67.28)
  BOTTOM w0.121: R55.2 47.96,71.17 v1(48.55,70.58) ; D17.1 9.08,52.96 9.23,53.11 v1(9.23,54.33)
I2C4_SDA: length 77.6
  TOP w0.121: J1.2 7.64,58.86 7.53,58.75 v1(7.53,57.5) ; J14.50 22.75,55.36 v1(23.15,54.96)
  LYR3 w0.121: v1(20.99,67.66) 20.99,67.31 20.59,66.91 20.59,64.41 20.1,63.92 20.1,60.83 23.15,57.78 v1(23.15,54.96)
  LYR4 w0.121: v1(20.99,67.66) 21.34,67.66 21.61,67.39 42.31,67.39 45.55,70.63 47.59,70.63 v1(48.55,71.59) 48.91,71.95 49.08,71.95 J19.3 ; v1(23.15,54.96) 22.39,54.96 20.1,57.25 17.31,57.25 16.42,58.14 14.99,58.14 14.36,57.5 v1(7.53,57.5)
  BOTTOM w0.121: D18.1 10.09,54.05 8.92,55.22 8.92,55.6 7.53,56.99 v1(7.53,57.5) ; v1(48.55,71.59) 48.3,71.84 48.3,71.95 48.12,72.13 R54.2
I2S2_CK: length 54.2
  TOP w0.121: J14.2 13.15,55.42 13,55.27 13,54.25 13.67,53.58 14.8,53.58 v1(15.27,53.11)
  LYR3 w0.121: J19.12 52.74,62.91 v1(52.74,55.34)
  LYR4 w0.121: v1(15.27,53.11) 15.27,52.42 16.28,51.41 21.25,51.41 22.61,52.78 30.11,52.78 32.55,55.22 52.26,55.22 52.39,55.34 v1(52.74,55.34)
I2S2_SDI: length 59.7
  TOP w0.121: J14.32 v1(19.15,55.36)
  LYR4 w0.121: v1(19.15,55.36) 20.06,54.45 29.75,54.45 31.78,56.49 44.23,56.49 44.48,56.74 46.39,56.74 v1(47.02,56.11)
  BOTTOM w0.121: v1(47.02,56.11) 47.4,55.72 47.4,54.96 49.69,52.68 51.82,52.68 52.52,51.98 52.52,32.19 J19.38
I2S2_SDO: length 68.2
  TOP w0.121: v1(19.46,53.95) 18.32,53.95 18.07,54.2 16.93,54.2 16.81,54.07 13.88,54.07 13.5,54.45 13.5,54.89 13.95,55.34 J14.6
  LYR4 w0.121: v1(19.46,53.95) 30.26,53.95 32.04,55.72 44.61,55.72 44.86,55.98 46.01,55.98 46.13,55.85 46.39,55.6 v1(46.9,55.6)
  BOTTOM w0.121: v1(46.9,55.6) 46.9,55.06 49.66,52.3 51.85,52.3 52.27,51.87 52.27,29.9 J19.40
I2S2_WS: length 60.3
  TOP w0.121: J14.4 13.55,55.47 13.25,55.17 13.25,54.35 13.77,53.83 16.91,53.83 17.03,53.95 17.81,53.95 18.19,53.57 v1(19.08,53.57)
  LYR4 w0.121: v1(19.08,53.57) 19.44,53.57 19.44,53.57 19.62,53.57 19.74,53.69 30.51,53.69 32.29,55.47 45.27,55.47 45.4,55.6 v1(45.75,55.6)
  BOTTOM w0.121: v1(45.75,55.6) 45.75,47.22 48.04,44.93 48.04,44.29 49.82,42.52 49.82,34.9 J19.35
ISET: length 4.3
  BOTTOM w0.121: U5.48 20.49,41.49 20.73,41.25 20.73,39.28 21.49,38.53 R105.1
LED_MODE: length 4
  BOTTOM w0.121: U5.41 20.54,44.99 20.77,44.77 C80.1 21.96,44.77 22,44.72 R94.1 R95.2
LPO_32K: length 22.8
  TOP w0.121: v1(33.43,43.28) 33.51,43.2 J10.49 ; v1(34.94,58.76) 34.96,58.76 34.98,58.77 35.09,58.77 35.3,58.99 R39.2 34.77,59.47 34.74,59.43 R38.2
  LYR3 w0.121: v1(34.94,58.76) 37.12,56.58 37.12,50.75 36.88,50.52 36.1,50.52 32.67,47.09 32.67,44.04 v1(33.43,43.28)
MDC: length 3
  BOTTOM w0.121: R73.2 19.5,48.43 18.96,47.89 U5.36
MDIO: length 2.1
  BOTTOM w0.121: U5.37 20.74,46.99 21.17,47.42 R84.2
MOC1: length 33.6
  TOP w0.121: J14.67 26.35,58.29 25.57,57.51 24.83,57.5 v1(22.13,57.5)
  LYR4 w0.121: v1(22.13,57.5) 22.82,57.5 23.05,57.27 23.05,56.46 22.82,56.23 21.55,56.23 20.28,57.5 18.83,57.5 17.94,58.39 14.84,58.39 14.23,57.78 9.87,57.78 9.75,57.9 9.75,58.27 9.63,58.39 9.39,58.39 9.27,58.27 9.27,57.9 9.15,57.78 8.9,57.78 8.78,57.9 8.78,58.27 8.66,58.39 8.42,58.39 8.3,58.27 8.3,57.9 8.18,57.78 7.83,57.78 7.65,57.96 7.15,57.96 6.72,57.54 6.72,57.37 7.09,57 7.09,56.83 6.91,56.66 6.74,56.66 6.38,57.02 6.21,57.02 6.04,56.85 6.04,56.68 6.4,56.32 6.4,56.15 5.72,55.47 5.06,55.47 4.88,55.65 4.88,56.05 v1(4.9,56.07)
  BOTTOM w0.121: J22.13 v1(4.9,56.07)
MOC2: length 27.9
  TOP w0.121: v1(52,62.48) 52.38,62.86 52.38,67.89 J19.7 ; v1(48.29,47.2) 48.04,47.45 47.94,47.45 47.79,47.6 J7.44
  LYR3 w0.121: v1(48.29,47.2) 47.89,47.6 47.89,49.86 48.93,50.9 48.93,53.18 48.42,53.69 48.42,58.01 50.58,60.17 51.87,60.17 52.26,60.55 52.26,62.23 v1(52,62.48)
NRST: length 157.7
  TOP w0.121: SW1.4 SW1.2 v1(3.67,7.54) ; v1(7.65,16.99) 5.37,14.7 2.07,14.7 1.79,14.42 Q1.1 1.91,13.66 R2.2 C1.1 D1.1 1.81,10.64 v1(1.81,10.26) ; v1(39.78,32.86) 40.42,33.5 40.42,36.93 40.93,37.44 40.93,37.44 40.93,45.92 40.81,46.04 40.81,46.35 40.93,46.48 40.93,47.19 41.05,47.31 41.05,47.37 42.48,48.8 J7.49
  LYR3 w0.121: v1(4.35,52.55) 4.35,63.2 9.35,68.2 12.69,68.2 14.51,70.02 14.51,73.63 14.27,73.87 v1(14.27,73.89)
  LYR4 w0.121: v1(23.27,28.04) 18.32,28.04 18.19,27.91 15.85,27.91 14.13,29.63 14.13,34.64 5.24,43.53 5.24,45.91 5.27,45.94 5.27,52.26 4.99,52.55 v1(4.35,52.55) ; v1(23.27,28.04) 23.27,24.36 21.5,22.58 15.65,22.58 10.07,16.99 v1(7.65,16.99) ; v1(23.27,28.04) 23.63,28.04 23.75,27.91 25.69,27.91 26.07,28.29 35.21,28.29 v1(39.78,32.86)
  BOTTOM w0.121: TP12.1 9.65,80.64 14.27,76.01 v1(14.27,73.89) ; R128.1 21.47,28.57 22,28.04 v1(23.27,28.04) ; v1(1.81,10.26) 3.67,8.4 v1(3.67,7.54)
OTG_CC1: length 13.1
  TOP w0.121: v1(10.35,34.03) 9.76,34.03 9.24,33.51 J2.A5
  LYR3 w0.121: v1(13.37,28.17) 12.48,28.17 10.35,30.3 v1(10.35,34.03)
  BOTTOM w0.121: R122.1 v1(10.35,34.03) ; v1(13.37,28.17) 13.43,28.23 U2.3
OTG_CC2: length 6.8
  TOP w0.121: v1(10.04,29.56) 9.09,30.51 J2.B5
  BOTTOM w0.121: 11.97,28.23 11.27,28.23 11.08,28.42 11.08,29.13 10.66,29.55 R121.1 10.59,29.56 v1(10.04,29.56)
OTG_FS_DM: length 56.6
  TOP w0.114: v1(12.73,32.1) 12.62,32.22 11.84,32.22 11.44,32.62 11.44,33.49 11.86,33.91 18.47,33.91 19.24,34.67 24.17,34.67 v1(24.42,34.91) ; v1(41.69,52.21) 41.45,52.46 36.26,52.46 36.2,52.4 J10.3
  LYR3 w0.127: v1(41.69,52.21) 41.92,52.45 42.89,52.45 43.57,51.76 43.57,51.33 43.44,51.2 43.42,51.2 43.29,51.07 43.29,50.82 43.42,50.69 43.44,50.69 43.57,50.57 43.57,50.31 43.44,50.18 43.42,50.18 43.29,50.06 43.29,49.8 43.42,49.68 43.44,49.68 43.57,49.55 43.57,49.3 43.44,49.17 43.42,49.17 43.29,49.04 43.29,48.79 43.42,48.66 43.44,48.66 43.57,48.53 43.57,48.28 43.44,48.15 43.42,48.15 43.29,48.03 43.29,47.77 43.42,47.64 43.44,47.64 43.57,47.52 43.57,46.3 33.61,36.34 28.74,36.34 27.07,34.68 24.65,34.68 v1(24.42,34.91)
  BOTTOM w0.114: v1(12.73,32.1) 12.56,31.93 L6.4 12.03,31.82 R120.1
OTG_FS_DP: length 56.5
  TOP w0.114: v1(12.73,32.61) 12.62,32.5 11.96,32.5 11.72,32.74 11.72,33.37 11.97,33.63 13.27,33.63 13.38,33.51 13.38,33.41 13.5,33.3 13.72,33.3 13.84,33.41 13.84,33.51 13.95,33.63 14.18,33.63 14.3,33.51 14.3,33.36 14.41,33.25 14.64,33.25 14.75,33.36 14.75,33.51 14.87,33.63 18.59,33.63 19.35,34.39 24.17,34.39 v1(24.42,34.14) ; J10.1 36.2,52.8 36.26,52.74 41.44,52.74 v1(41.69,52.98)
  LYR3 w0.127: v1(24.42,34.14) 24.65,34.38 27.2,34.38 28.86,36.04 33.74,36.04 43.87,46.17 43.87,51.89 43.01,52.75 41.92,52.75 v1(41.69,52.98)
  BOTTOM w0.114: R118.1 12.1,32.81 L6.1 12.56,32.78 v1(12.73,32.61)
OTG_FS_ID: length 4.2
  TOP w0.121: v1(14.52,55.09) 14.77,55.34 15.03,55.34 15.15,55.46 J14.12
  BOTTOM w0.121: TP14.1 14.51,55.1 v1(14.52,55.09) 14.52,54.71 R123.2 14.49,54.62 15.02,54.09 15.02,53.97 15.26,53.73 R124.1
OTG_USB_DM: length 15.3
  TOP w0.114: v1(5.59,33) 5.6,33.01 J2.B7 ; v1(5.59,32.01) J2.A7 7.28,32.01 7.45,32.19 7.66,32.19 v1(7.91,31.94) 8.18,32.22 10.21,32.22 11.46,30.96 11.69,30.96 11.81,30.84 11.81,30.62 11.92,30.5 12.15,30.5 12.26,30.62 12.26,30.84 12.38,30.96 v1(12.86,30.96)
  BOTTOM w0.114: 11.97,30.13 12.59,30.13 12.86,30.4 v1(12.86,30.96) ; v1(5.59,33) v1(5.59,32.01) ; v1(7.91,31.94) 8.15,32.19 9.61,32.19 9.86,31.93 L6.3 10.39,31.82 R120.2
OTG_USB_DP: length 15.9
  TOP w0.114: v1(13.5,30.96) 13.11,31.34 11.48,31.34 10.32,32.5 8.12,32.5 v1(7.91,32.71) 7.66,32.47 7.33,32.47 7.28,32.51 J2.A6 5.4,32.51 5.11,32.23 5.11,31.85 5.45,31.51 J2.B6
  BOTTOM w0.114: v1(13.5,30.96) 13.5,30.25 13.61,30.13 U2.1 ; v1(7.91,32.71) 8.15,32.47 9.61,32.47 9.92,32.78 L6.2 10.32,32.81 R118.2
OTG_VBUS: length 42.2
  TOP w0.203: J10.7 36.95,51.6
  TOP w0.406: v1(41.56,51.15) 41.12,51.6 36.95,51.6 ; v1(18.07,34.9) 19.34,36.17 v1(26.32,36.17)
  LYR3 w0.406: v1(41.56,51.15) 42.53,50.19 42.53,46.4 34.09,37.97 28.13,37.97 v1(26.32,36.17)
  BOTTOM w0.406: R125.1 17.84,34.67 v1(18.07,34.9)
PONKEYN: length 86.8
  TOP w0.121: J7.45 42.09,48 41.18,47.09 v1(41.18,46.2) ; SW2.2 SW2.4 9.56,78.89 v1(9.56,77.82) ; v1(13.9,75.16) 14,75.26 C102.1
  LYR3 w0.121: v1(8.03,50.14) 7.53,49.63 4.73,49.63 3.46,50.9 3.46,63.34 9.05,68.93 12.48,68.93 13.11,69.57 13.11,74.77 13.5,75.16 v1(13.9,75.16)
  LYR4 w0.121: v1(8.03,50.14) 8.03,49.12 8.92,48.23 12.71,48.23 13.6,47.34 21.62,47.34 23.4,45.56 27.06,45.56 27.31,45.32 34.22,45.32 34.6,45.69 38.26,45.69 38.77,46.2 v1(41.18,46.2) ; v1(13.9,75.16) 13.9,75.64 12.09,77.45 9.93,77.45 v1(9.56,77.82)
QSPI_BK2_IO0: length 26
  TOP w0.121: v1(40.67,49.63) 39.79,48.74 36.81,48.74 36.36,49.2 J10.19 ; v1(50.2,49.25) 50.2,54.58 50.58,54.96 53.42,54.96 53.78,55.32 J19.18
  LYR4 w0.121: v1(50.2,49.25) 49.85,49.25 49.72,49.12 41.18,49.12 v1(40.67,49.63)
QSPI_BK2_IO1: length 22.3
  TOP w0.121: v1(40.67,48.86) 40.29,48.48 36.73,48.48 36.41,48.8 J10.21
  LYR3 w0.121: J19.22 52.61,50.09 52.61,48.1 52.1,47.6 v1(50.33,47.6)
  LYR4 w0.121: v1(50.33,47.6) 49.33,48.59 45.48,48.59 45.12,48.23 41.75,48.23 41.62,48.36 41.46,48.36 41.46,48.36 41.17,48.36 v1(40.67,48.86)
QSPI_BK2_IO2: length 28.9
  TOP w0.121: v1(39.15,47.22) 38.64,47.72 37.13,47.72 36.46,48.4 J10.23
  BOTTOM w0.121: J19.37 49.56,32.61 49.56,42.39 45.13,46.82 39.54,46.82 v1(39.15,47.22)
QSPI_BK2_IO3: length 30.8
  TOP w0.121: J10.25 36.51,48 37.04,47.47 38.13,47.47 v1(38.51,47.09) ; v1(49.94,46.96) 49.81,47.09 49.81,59.98 J19.13
  LYR4 w0.121: v1(38.51,47.09) 38.78,46.82 42.31,46.82 43.06,47.57 49.33,47.57 v1(49.94,46.96)
QSPI_BK2_NCS: length 33
  TOP w0.121: J14.52 23.15,55.46 23.27,55.34 v1(23.53,55.34)
  LYR4 w0.121: J19.16 52.54,57.63 44.36,57.63 43.47,56.74 31.53,56.74 31.02,56.23 24.42,56.23 v1(23.53,55.34)
QSPI_CLK: length 28.2
  TOP w0.121: J14.66 25.95,57.26 26.2,57.5 26.96,57.5 27.97,56.49 31.12,56.49 32.04,57.41 32.04,57.51 v1(32.29,57.76)
  LYR4 w0.121: J19.15 50.5,58.14 40.55,58.14 39.66,57.25 33.41,57.25 32.9,57.76 v1(32.29,57.76)
R/LINPUT1: length 45
  LYR4 w0.305: v1(44.86,61.57) 43.75,61.57 42.99,62.33 42.1,62.33 39.81,64.61 27.97,64.61 26.32,66.27 18.58,66.27 17.31,67.54 16.16,67.54 v1(15.27,66.65)
  BOTTOM w0.305: R116.2 45.17,61.57 v1(44.86,61.57) ; v1(15.27,66.65) 15.27,66.56 FB11.1 14.71,66.21 C68.1 12.99,66.21 12.81,66.39 U14.3 11.52,67.18 13.11,68.77 13.11,71.33 12.1,72.35 12.1,72.6
  BOTTOM w0.381: 12.1,72.6 CON1.1 12.1,73.1
RGMII1_RCLK: length 4.6
  BOTTOM w0.121: U5.35 18.46,48.65 18.88,49.06 R70.1 18.94,49.44 19.46,49.97 19.46,51 18.94,51.52 R61.2
RGMII1_RCTL: length 6.7
  BOTTOM w0.121: R53.2 18.48,53 18.32,52.84 18.32,51.92 17.93,51.52 ; 17.93,51.52 18.32,51.13 18.32,49.87 17.93,49.47 R66.1 17.86,49.09 17.46,48.69 U5.33 ; 17.93,51.52 R60.1
RGMII1_RD0: length 4.3
  BOTTOM w0.121: R59.2 16.91,51.52 17.31,51.13 17.31,49.84 16.91,49.45 R69.1 16.85,49.07 16.96,48.95 U5.32
RGMII1_RD1: length 4.5
  BOTTOM w0.121: 15.89,49.45 16.46,48.88 U5.31 ; 15.89,49.45 R68.1 ; 15.89,49.45 16.29,49.84 16.29,51.13 15.89,51.52 R58.2
RGMII1_RD2: length 4.3
  BOTTOM w0.121: U5.28 14.96,48.96 14.82,49.11 R64.1 14.88,49.49 15.27,49.89 15.27,51.13 14.88,51.52 R57.2
RGMII1_RD3: length 4.5
  BOTTOM w0.121: R56.2 13.86,51.52 14.24,51.14 14.24,49.86 13.86,49.48 R65.1 13.8,49.07 14.46,48.41 U5.27
RGMII1_TCLK: length 24.4
  TOP w0.121: R48.2 13.74,62.3 13.43,61.99 13.34,61.99 C20.1 v1(12.33,61.54)
  LYR3 w0.121: v1(12.33,61.54) 11.59,60.8 11.59,60.33 11.71,60.21 11.8,60.21 11.92,60.09 11.92,59.85 11.8,59.73 11.71,59.73 11.59,59.61 11.59,59.37 11.71,59.25 11.8,59.25 11.92,59.13 11.92,58.88 11.8,58.76 11.71,58.76 11.59,58.64 11.59,58.4 11.71,58.28 11.8,58.28 11.92,58.16 11.92,57.92 11.8,57.8 11.71,57.8 11.59,57.68 11.59,57.44 11.71,57.32 11.8,57.32 11.92,57.2 11.92,56.95 11.8,56.83 11.71,56.83 11.59,56.71 11.59,54.92 11.71,54.8 11.86,54.8 11.98,54.68 11.98,54.44 11.86,54.32 11.71,54.32 11.59,54.2 11.59,53.96 11.71,53.83 11.86,53.83 11.98,53.71 11.98,53.47 11.86,53.35 11.71,53.35 11.59,53.23 11.59,52 11.71,51.88 12.26,51.88 12.38,51.76 12.38,51.52 12.26,51.4 11.71,51.4 11.59,51.28 11.59,51.04 11.71,50.92 12.49,50.92 12.61,50.8 12.61,50.55 12.49,50.43 11.71,50.43 11.59,50.31 11.59,50.07 11.71,49.95 12.26,49.95 12.38,49.83 12.38,49.59 12.26,49.47 11.71,49.47 11.59,49.35 11.59,47.95 11.84,47.69 v1(11.84,47.09)
  BOTTOM w0.121: U5.24 12.19,46.99 12.1,47.09 v1(11.84,47.09)
RGMII1_TCTL: length 26.1
  TOP w0.121: v1(17.86,63.17) 18.13,62.9 18.13,62.62 18.44,62.3 R41.2
  LYR3 w0.121: v1(12.59,47.83) 12.17,48.24 12.17,48.82 12.94,49.58 12.94,51.61 12.2,52.35 12.2,53.26 12.4,53.46 12.4,54.91 11.97,55.34 11.97,56.44 12.36,56.83 12.36,60.44 13.01,61.08 15.72,61.08 15.84,60.96 15.84,60.49 15.96,60.37 16.2,60.37 16.32,60.49 16.32,60.96 16.44,61.08 16.68,61.08 16.8,60.96 16.8,60.49 16.92,60.37 17.17,60.37 17.29,60.49 17.29,60.96 17.86,61.54 v1(17.86,63.17)
  BOTTOM w0.121: U5.25 13.46,47.89 13.25,48.1 12.87,48.1 12.84,48.08 12.83,48.08 v1(12.59,47.83)
RGMII1_TD0: length 24.9
  TOP w0.121: v1(14.13,63.22) 14.52,62.83 14.52,62.48 R46.2
  LYR3 w0.121: v1(11.46,44.42) 10.24,45.64 10.24,61.92 11.54,63.22 v1(14.13,63.22)
  BOTTOM w0.121: U5.19 11.89,44.49 11.82,44.42 v1(11.46,44.42)
RGMII1_TD1: length 25.4
  TOP w0.121: R45.2 15.58,62.68 15.43,62.84 15.27,62.84 v1(14.89,63.22)
  LYR3 w0.121: v1(14.89,63.22) 14.89,62.58 14.69,62.38 13.65,62.38 13.42,62.61 11.34,62.61 10.6,61.87 10.6,45.67 11.34,44.93 v1(11.84,44.93)
  BOTTOM w0.121: U5.20 11.91,44.99 v1(11.84,44.93)
RGMII1_TD2: length 25.8
  TOP w0.121: v1(15.78,63.22) 16.1,62.9 16.1,62.62 16.41,62.3 R44.2
  LYR3 w0.121: v1(15.78,63.22) 16.03,62.97 16.03,62.35 15.55,61.87 13.39,61.87 12.96,62.3 11.49,62.3 10.93,61.74 10.93,46.32 11.46,45.79 v1(11.46,45.44)
  BOTTOM w0.121: v1(11.46,45.44) 11.52,45.49 U5.21
RGMII1_TD3: length 25.9
  TOP w0.121: v1(16.8,63.22) 17.05,62.97 17.2,62.97 17.48,62.68 R43.2
  LYR3 w0.121: v1(11.59,46.45) 11.29,46.76 11.29,61.64 11.62,61.97 12.61,61.97 13.09,61.49 16.85,61.49 17.23,61.87 17.23,62.79 v1(16.8,63.22)
  BOTTOM w0.121: v1(11.59,46.45) 12.05,45.99 U5.22
SAI2_FSAM: length 21.7
  TOP w0.121: J10.16 30.25,50 29.62,49.37 29.62,48.61 29.37,48.35 29.24,48.35 v1(28.99,48.1)
  LYR4 w0.121: v1(28.99,48.1) 29.62,48.1 29.75,48.23 30.51,48.23 30.86,47.88 39.31,47.88 39.53,48.1 v1(39.91,48.1)
  BOTTOM w0.121: R145.1 39.15,48.87 v1(39.91,48.1)
SAI2_MCLKA: length 19.9
  TOP w0.121: v1(30.13,47.84) 30.53,48.24 30.53,48.88 30.85,49.2 J10.20
  LYR4 w0.121: v1(30.13,47.84) 30.59,47.84 30.77,47.66 39.24,47.66 39.3,47.6 v1(39.66,47.6)
  BOTTOM w0.121: R137.1 41.03,50.16 41.05,50.14 41.05,48.22 40.43,47.6 v1(39.66,47.6)
SAI2_SCKAM: length 20.9
  TOP w0.121: v1(28.99,48.74) 28.99,49.37 30.01,50.4 J10.14
  LYR4 w0.121: v1(28.99,48.74) 29.24,48.49 30.58,48.49 30.96,48.1 38.9,48.1 40.17,49.37 v1(40.17,49.88)
  BOTTOM w0.121: R140.1 40.04,53.06 39.91,52.93 39.91,50.14 v1(40.17,49.88)
SAI2_SDAM: length 16.7
  TOP w0.121: v1(30.13,48.87) 30.13,49.22 30.51,49.6 J10.18
  LYR4 w0.121: v1(38.64,49.25) 38.64,48.87 38.13,48.36 31.02,48.36 30.51,48.87 v1(30.13,48.87)
  BOTTOM w0.121: v1(38.64,49.25) 38.26,49.63 R148.1
SAI2_SDBM: length 12.9
  TOP w0.121: v1(31.28,48.74) 31.33,48.8 J10.22
  LYR4 w0.121: v1(37.63,49.25) 37.12,48.74 v1(31.28,48.74)
  BOTTOM w0.121: R157.1 36.48,52.8 38.01,51.28 38.01,49.63 v1(37.63,49.25)
SD_CD: length 5.5
  BOTTOM w0.121: J21.10 21.58,70.22 20.81,70.99 D12.1 18.28,70.99 18.27,70.98 R146.2 17.7,70.96 R143.2
SD_CLK: length 55.4
  TOP w0.121: v1(27.96,46.95) 28.22,46.7 C14.1 R37.2
  LYR3 w0.121: v1(39.75,82.9) 37.46,80.62 34.45,80.62 31.28,77.44 31.28,62.84 32.42,61.69 32.42,58.4 35.72,55.1 35.72,51.77 34.22,50.26 33.56,50.26 30.25,46.95 v1(27.96,46.95)
  BOTTOM w0.121: v1(39.75,82.9) R81.2 39.75,82.18 39.33,81.76 38.22,81.76 37.8,82.18 D5.1 37.42,82.24 37.36,82.31 J21.5
SD_CMD: length 6.2
  BOTTOM w0.121: J21.3 19.25,81.61 18.67,81.03 ; R154.2 R153.2 16.62,80.97 17.1,81.45 18.25,81.45 18.67,81.03 ; 18.67,80.97 D13.1 18.67,81.03
SD_DAT0: length 6.2
  BOTTOM w0.121: J21.7 37.1,80.91 37.42,81.23 D6.1 37.8,81.17 38.25,80.72 39.02,80.72 39.53,81.23 R82.2 R83.2
SD_DAT1: length 4.5
  BOTTOM w0.121: J21.8 37.42,80.21 37.42,80.21 D7.1 R92.2 R93.2
SD_DAT2: length 4.6
  BOTTOM w0.121: J21.1 19.88,80.21 18.67,79 D15.1 R141.2 R142.2
SD_DAT3: length 6.6
  BOTTOM w0.121: J21.2 19.56,80.91 18.67,80.01 D14.1 18.67,79.56 18.58,79.47 16.72,79.47 16.24,79 R155.2 R156.2
SDMMC1_CD: length 51.7
  TOP w0.121: v1(8.4,52.67) 8.8,53.06 12.79,53.06 14.17,51.67 19.05,51.67 22.75,47.98 26.2,47.98 26.96,47.22 26.96,45.56 27.38,45.14 30.44,45.14 30.5,45.2 J10.40
  LYR3 w0.121: v1(18.46,69.55) 15.67,69.55 8.8,62.68 8.8,53.41 8.4,53.02 v1(8.4,52.67)
  BOTTOM w0.121: R143.1 v1(18.46,69.55)
